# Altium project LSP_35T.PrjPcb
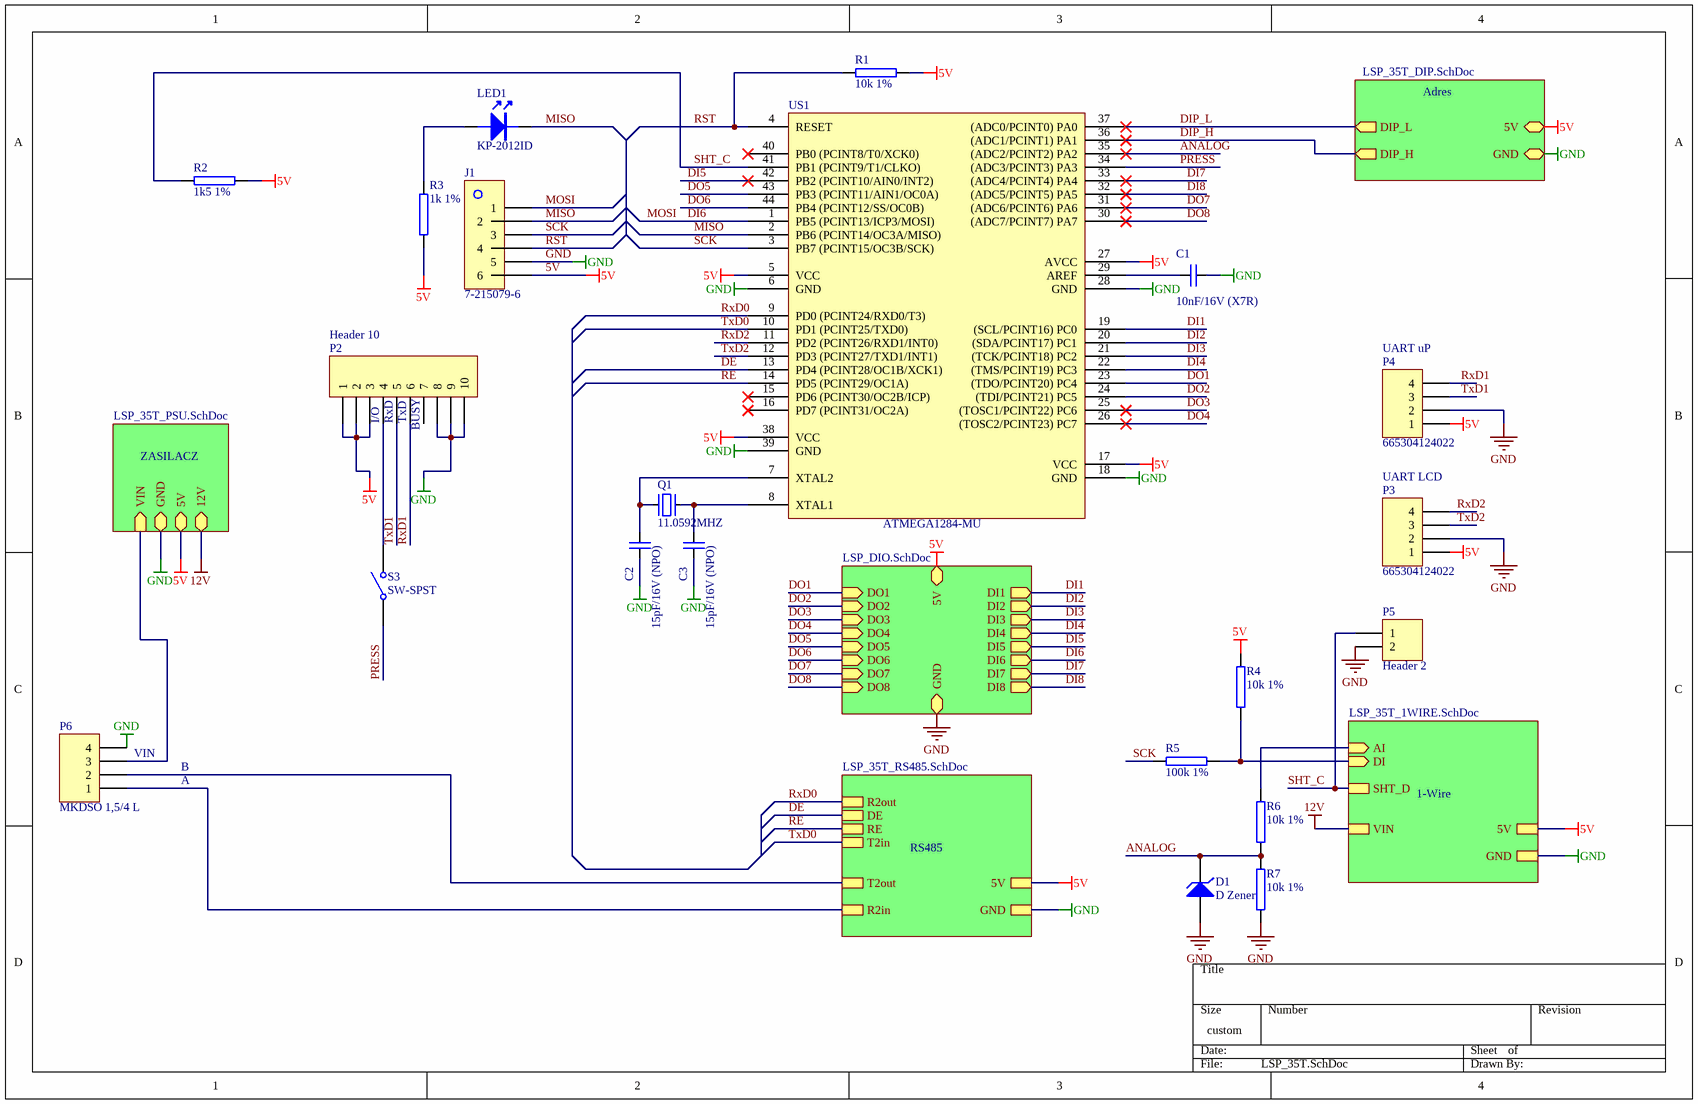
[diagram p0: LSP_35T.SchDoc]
6 sheets, 138 parts. Net scope: hierarchical (ports join the sheet entries above them; power ports are global).
Board files: LSP_35T_Polygon.PcbDoc, LSP_35T.PcbDoc
Sheets:
  LSP_35T.SchDoc
    ZASILACZ = LSP_35T_PSU.SchDoc
    RS485 = LSP_35T_RS485.SchDoc
    Adres = LSP_35T_DIP.SchDoc
    1-Wire = LSP_35T_1WIRE.SchDoc
     = LSP_DIO.SchDoc

## Sheet LSP_35T.SchDoc
size 317 x 205 mm; SheetNumber: 0; SheetTotal: 0

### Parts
C1  10nF/16V (X7R)  [0402]
C2  15pF/16V (NPO)  [0402]
C3  15pF/16V (NPO)  [0402]
D1  D Zener  [minimelf]
J1  7-215079-6  [PRZ_MICROMATCH-6]
LED1  KP-2012ID  [0402d]
P2  Header 10  [FFC/SM1.0-2H10]
P3  665304124022  [665304124022]
P4  665304124022  [665304124022]
P5  Header 2  [665302124022]
P6  MKDSO 1,5/4 L  [HDR1X4]
Q1  11.0592MHZ  [ABM3B]
R1  10k 1%  [0402]
R2  1k5 1%  [0402]
R3  1k 1%  [0402]
R4  10k 1%  [0402]
R5  100k 1%  [0402]
R6  10k 1%  [0402]
R7  10k 1%  [0402]
S3  SW-SPST  [416131160802]
US1  ATMEGA1284-MU  [44A_M]

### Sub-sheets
1-Wire = LSP_35T_1WIRE.SchDoc: AI (in), VIN, GND, 5V, DI (in), SHT_D  | Description: RS485
Adres = LSP_35T_DIP.SchDoc: DIP_L (out), GND (bidir), 5V (bidir), DIP_H (out)  | Description: RS485
RS485 = LSP_35T_RS485.SchDoc: R2out, T2in, T2out, GND, 5V, R2in, DE, RE  | Description: RS485
ZASILACZ = LSP_35T_PSU.SchDoc: VIN (in), GND (bidir), 5V (bidir), 12V (bidir)  | Description: ZASILACZ
? = LSP_DIO.SchDoc: DO1 (in), DO2 (in), DO3 (in), DO4 (in), DO5 (in), DO6 (in), DO7 (in), DO8 (in), DI1 (out), DI2 (out), DI3 (out), DI4 (out), DI5 (out), DI6 (out), DI7 (out), DI8 (out), GND (bidir), 5V (bidir)

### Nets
5V: J1.6 P2.1 P2.2 P2.3 P3.1 P4.1 R1.2 R2.1 R3.1 R4.2 US1.5(VCC) US1.17(VCC) US1.27(AVCC) US1.38(VCC) ; sheet ZASILACZ/5V, sheet RS485/5V, sheet Adres/5V, sheet 1-Wire/5V, sheet /5V
12V: sheet ZASILACZ/12V, sheet 1-Wire/VIN
GND: C1.2 C2.1 C3.1 D1.1(A) J1.5 P2.8 P2.9 P2.10 P3.2 P4.2 P5.2 P6.4 R7.1 US1.6(GND) US1.18(GND) US1.28(GND) US1.39(GND) ; sheet ZASILACZ/GND, sheet RS485/GND, sheet Adres/GND, sheet 1-Wire/GND, sheet /GND
A: P6.1 ; sheet RS485/R2in
ANALOG: D1.2(K) R6.1 R7.2 US1.35((ADC2/PCINT2)_PA2)
B: P6.2 ; sheet RS485/T2out
DE: US1.13(PD4_(PCINT28/OC1B/XCK1)) ; sheet RS485/DE
DI1: US1.19((SCL/PCINT16)_PC0) ; sheet /DI1
DI2: US1.20((SDA/PCINT17)_PC1) ; sheet /DI2
DI3: US1.21((TCK/PCINT18)_PC2) ; sheet /DI3
DI4: US1.22((TMS/PCINT19)_PC3) ; sheet /DI4
DI5: US1.42(PB2_(PCINT10/AIN0/INT2)) ; sheet /DI5
DI6: J1.1 US1.1(PB5_(PCINT13/ICP3/MOSI)) ; sheet /DI6  [also labelled MOSI]
DI7: US1.33((ADC4/PCINT4)_PA4) ; sheet /DI7
DI8: US1.32((ADC5/PCINT5)_PA5) ; sheet /DI8
DIP_H: US1.36((ADC1/PCINT1)_PA1) ; sheet Adres/DIP_H
DIP_L: US1.37((ADC0/PCINT0)_PA0) ; sheet Adres/DIP_L
DO1: US1.23((TDO/PCINT20)_PC4) ; sheet /DO1
DO2: US1.24((TDI/PCINT21)_PC5) ; sheet /DO2
DO3: US1.25((TOSC1/PCINT22)_PC6) ; sheet /DO3
DO4: US1.26((TOSC2/PCINT23)_PC7) ; sheet /DO4
DO5: US1.43(PB3_(PCINT11/AIN1/OC0A)) ; sheet /DO5
DO6: US1.44(PB4_(PCINT12/SS/OC0B)) ; sheet /DO6
DO7: US1.31((ADC6/PCINT6)_PA6) ; sheet /DO7
DO8: US1.30((ADC7/PCINT7)_PA7) ; sheet /DO8
MISO: J1.2 LED1.2 US1.2(PB6_(PCINT14/OC3A/MISO))
PRESS: S3.1(COMMON) US1.34((ADC3/PCINT3)_PA3)
RE: US1.14(PD5_(PCINT29/OC1A)) ; sheet RS485/RE
RST: J1.4 R1.1 US1.4(RESET)
RxD0: US1.9(PD0_(PCINT24/RXD0/T3)) ; sheet RS485/R2out
RxD1: P2.6 P4.4
RxD2: P3.4 US1.11(PD2_(PCINT26/RXD1/INT0))
SCK: J1.3 R5.1 US1.3(PB7_(PCINT15/OC3B/SCK))
SHT_C: P5.1 R2.2 US1.41(PB1_(PCINT9/T1/CLKO)) ; sheet 1-Wire/SHT_D
TxD0: US1.10(PD1_(PCINT25/TXD0)) ; sheet RS485/T2in
TxD1: P2.5 P4.3
TxD2: P3.3 US1.12(PD3_(PCINT27/TXD1/INT1))
NetC1_1: C1.1 US1.29(AREF)
NetC2_2: C2.2 Q1.2 US1.7(XTAL2)
NetC3_2: C3.2 Q1.1 US1.8(XTAL1)
NetD5_1: P6.3 ; sheet ZASILACZ/VIN
NetLED1_1: LED1.1 R3.2
NetP2_4: P2.4 S3.2(NO)
NetP7_5: R4.1 R5.2 ; sheet 1-Wire/DI
NetP7_6: R6.2 ; sheet 1-Wire/AI

Not connected (* = marked no-connect by the designer): P2 7; US1 15(PD6_(PCINT30/OC2B/ICP))* 16(PD7_(PCINT31/OC2A))* 40(PB0_(PCINT8/T0/XCK0))*

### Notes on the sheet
- (near P4) UART uP
- (near P2) I/O
- (near P2) RxD
- (near P2) TxD
- (near P2) BUSY
- (near P3) UART LCD
- (near P6) VIN
- B
- A

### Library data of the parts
C1-C3 = _C_CER: Ceramic capacitor
D1 = D Zener: Zener Diode
LED1 = DIODA2: Dioda LED
P2 = Header 10: Header, 10-Pin
P3 P4 P6 = Header 4: Header, 4-Pin
P5 = Header 2: Header, 2-Pin
Q1 = 11.0592MHZ: Quartz 11,0592MHz, height 3,5mm
R1-R7 = RESSMD1: Rezystor
S3 = SW-SPST: Single-Pole, Single-Throw Switch
US1 = ATMEGA1284-AU

## Sheet LSP_35T_PSU.SchDoc
size A4; SheetNumber: 0; SheetTotal: 0
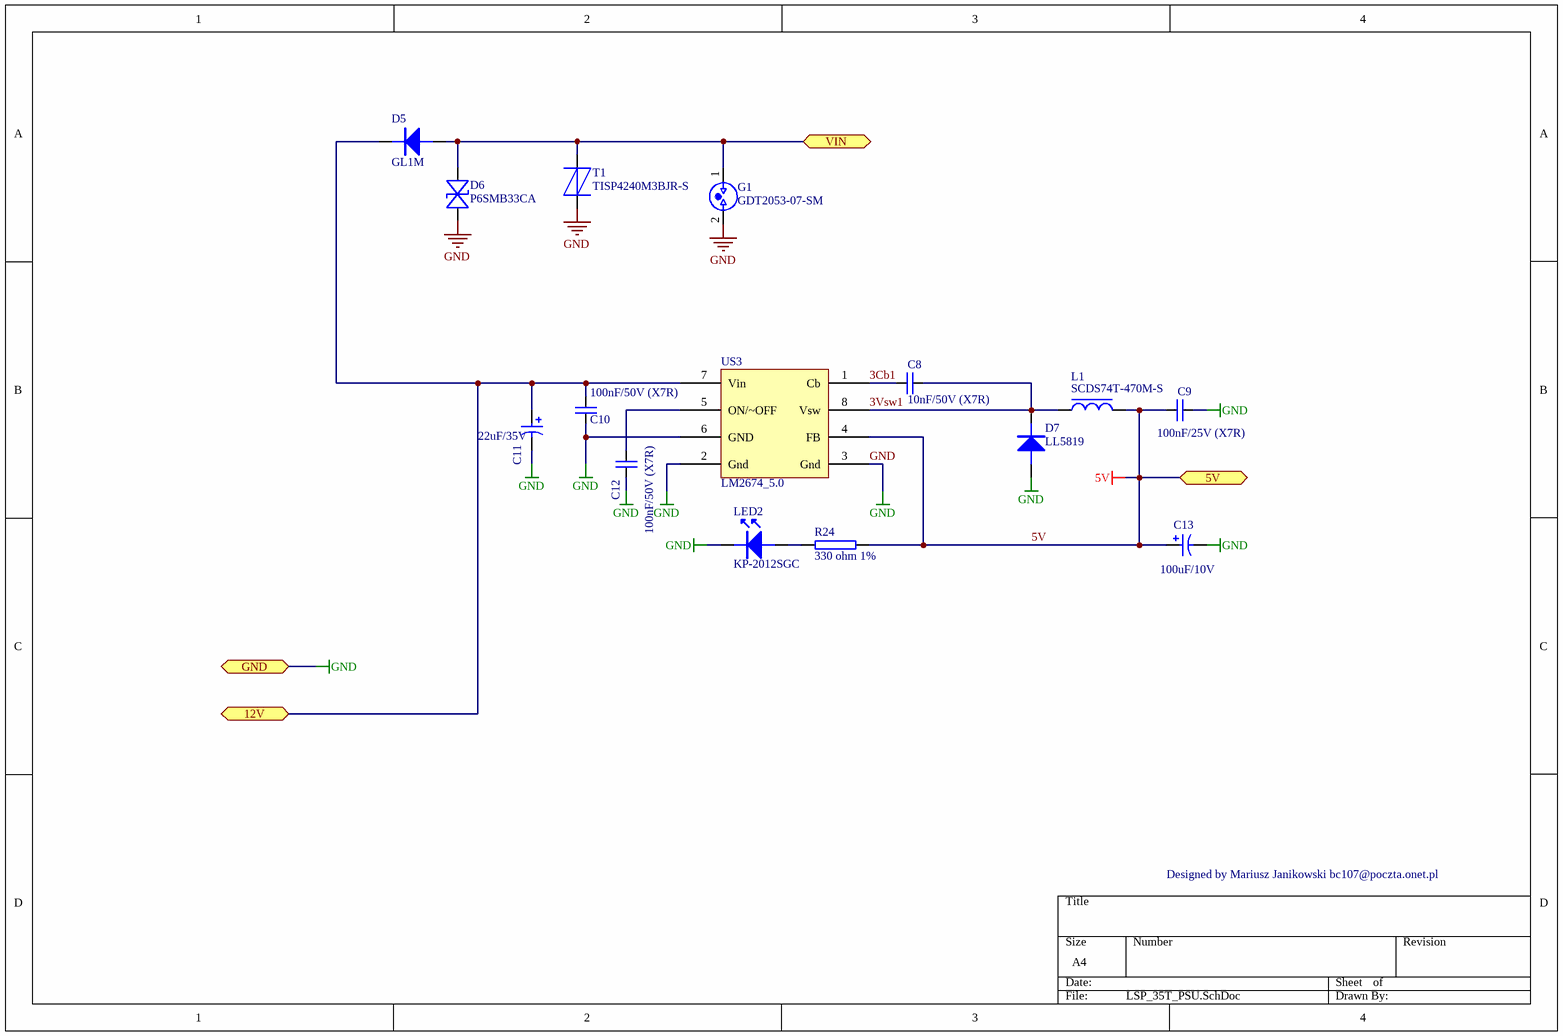
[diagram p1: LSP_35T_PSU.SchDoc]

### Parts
C8  10nF/50V (X7R)  [0402]
C9  100nF/25V (X7R)  [0402]
C10  100nF/50V (X7R)  [0402]
C11  22uF/35V  [SMD_C_TANTAL-D]
C12  100nF/50V (X7R)  [0402]
C13  value 100uF/10V  [TANTAL-B]  (hidden comment: 100uF/16V)
D5  GL1M  [minimelf]
D6  P6SMB33CA  [SMD_DO-214AA/SMB]
D7  LL5819  [SMD_MELF2]
G1  GDT2053-07-SM  [GDT2053]
L1  SCDS74T-470M-S  [SMD_SCDS74T]
LED2  KP-2012SGC  [0402D]
R24  330 ohm 1%  [0402]
T1  TISP4240M3BJR-S  [SMD_DO-214AA/SMB]
US3  LM2674_5.0  [SMD_SO-8]

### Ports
5V, 12V, GND, VIN

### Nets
5V: C9.2 C13.1 L1.2 R24.1 US3.4(FB) ; port 5V
12V: C10.2 C11.1 D5.2 US3.7(Vin) ; port 12V
GND: C9.1 C10.1 C11.2 C12.1 C13.2 D6.1 D7.1 G1.2 LED2.2 T1.2 US3.2(Gnd) US3.3(Gnd) US3.6(GND) ; port GND
3Cb1: C8.1 US3.1(Cb)
3Vsw1: C8.2 D7.2 L1.1 US3.8(Vsw)
NetC12_2: C12.2 US3.5(ON/~OFF)
NetD5_1: D5.1 D6.2 G1.1 T1.1 ; port VIN
NetLED2_1: LED2.1 R24.2

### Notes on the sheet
- Designed by Mariusz Janikowski bc107@poczta.onet.pl

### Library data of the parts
C8-C10 C12 = _C_CER: Ceramic capacitor
C11 C13 = CAP2: Bi-Polar Capacitor
D5 D7 = DIODA1: Dioda
D6 = P6SMB33CA: Transil diode 600W 33V bidirectional; Text Field1: Taiwan Semiconductor; Text Field2: TME
G1 = GDT_1
L1 = CEWKA2
LED2 = DIODA2: Dioda LED
R24 = RESSMD1: Rezystor
T1 = TISP
US3 = LM2675

## Sheet LSP_35T_RS485.SchDoc
size A4; SheetNumber: 0; SheetTotal: 0
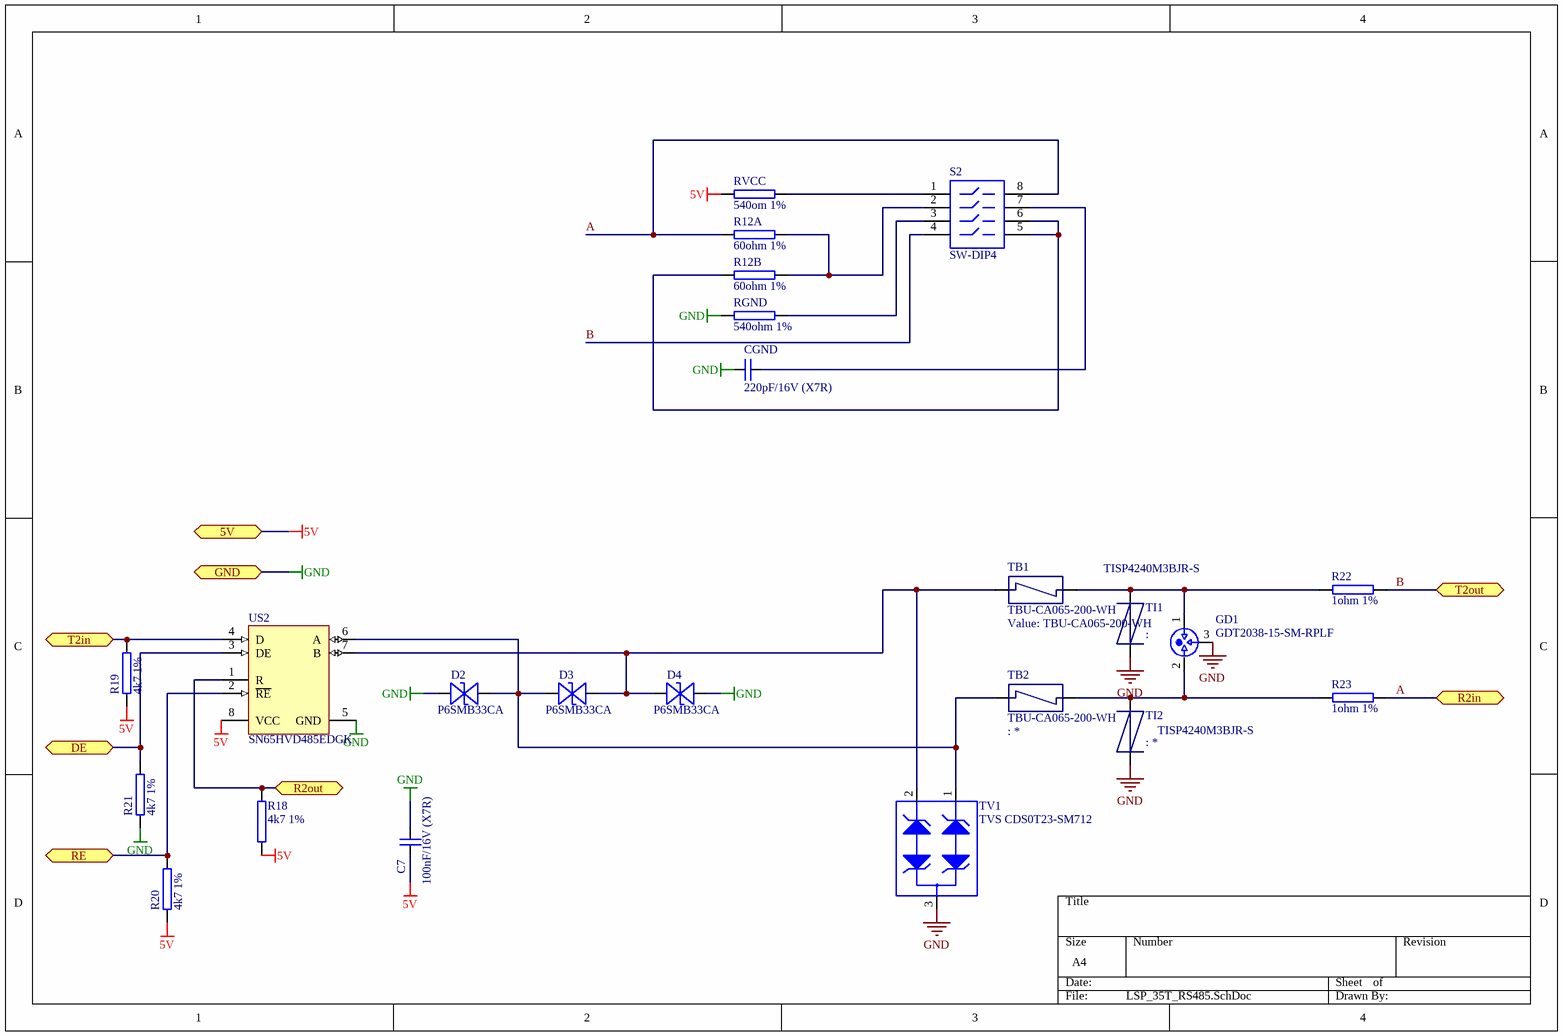
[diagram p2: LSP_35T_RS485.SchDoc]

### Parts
C7  100nF/16V (X7R)  [0402]
CGND  220pF/16V (X7R)  [0402]
D2  P6SMB33CA  [SMD_DO-214AA/SMB]
D3  P6SMB33CA  [SMD_DO-214AA/SMB]
D4  P6SMB33CA  [SMD_DO-214AA/SMB]
GD1  GDT2038-15-SM-RPLF  [GDT2038]
R12A  60ohm 1%  [0402]
R12B  60ohm 1%  [0402]
R18  4k7 1%  [0402]
R19  4k7 1%  [0402]
R20  4k7 1%  [0402]
R21  4k7 1%  [0402]
R22  1ohm 1%  [0402]
R23  1ohm 1%  [0402]
RGND  540ohm 1%  [0402]
RVCC  540om 1%  [0402]
S2  SW-DIP4  [418121270804]
TB1  TBU-CA065-200-WH  [TBU-CA]
TB2  TBU-CA065-200-WH  [TBU-CA]
TI1  TISP4240M3BJR-S  [SMD_DO-214AA/SMB]
TI2  TISP4240M3BJR-S  [SMD_DO-214AA/SMB]
TV1  TVS CDS0T23-SM712  [SOT23]
US2  SN65HVD485EDGK  [DGK8_L]

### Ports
5V, DE, GND, R2in, R2out, RE, T2in, T2out

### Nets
5V: C7.2 R18.1 R19.1 R20.2 RVCC.1 US2.8(VCC) ; port 5V
GND: C7.1 CGND.1 D2.2 D4.1 GD1.3 R21.2 RGND.1 TI1.2 TI2.2 TV1.3 US2.5(GND) ; port GND
A: R12A.1 R23.2 S2.8 ; port R2in
B: R22.2 S2.4 ; port T2out
DE: R21.1 US2.3(DE) ; port DE
RE: R20.1 US2.2(~{RE}) ; port RE
RxD0: R18.2 US2.1(R) ; port R2out
TxD0: R19.2 US2.4(D) ; port T2in
NetCGND_2: CGND.2 S2.7
NetD2_1: D2.1 D3.1 TB2.1 TV1.1 US2.6(A)
NetD3_2: D3.2 D4.2 TB1.1 TV1.2 US2.7(B)
NetGD1_1: GD1.1 R22.1 TB1.2 TI1.1
NetGD1_2: GD1.2 R23.1 TB2.2 TI2.1
NetR12A_2: R12A.2 R12B.2 S2.2
NetR12B_1: R12B.1 S2.5 S2.6
NetRGND_2: RGND.2 S2.3
NetRVCC_2: RVCC.2 S2.1

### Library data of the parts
C7 CGND = _C_CER: Ceramic capacitor
D2-D4 = P6SMB33CA: as D6 on sheet LSP_35T_PSU
GD1 = GDT
R12A R12B R18-R23 RGND RVCC = RESSMD1: Rezystor
S2 = SW-DIP4: DIP Switch
TB1 TB2 = TBU
TI1 TI2 = TISP
TV1 = TVS
US2 = SN65HVD485EDGK: Half Duplex RS-485 Transceiver, 10 Mbps, 5 V, -40 to 85 degC, 8-pin MSOP (DGK), Green (RoHS & no Sb/Br); Manufacturer: Texas Instruments; # of TX/RX: 1 TX / 1 RX; Drivers Per Package: 1; Number of Nodes: 64; Signaling Rate(Mbps): 10; Common Mode Range: -7 to 12; ESD(kV): 15; Fault Protection(V): -9 to 14; Fail Safe: Open; ICC(Max)(mA): 2; Supply Voltage(s)(V): 5; Rating: Catalog

## Sheet LSP_35T_DIP.SchDoc
size A4; SheetNumber: 0; SheetTotal: 0
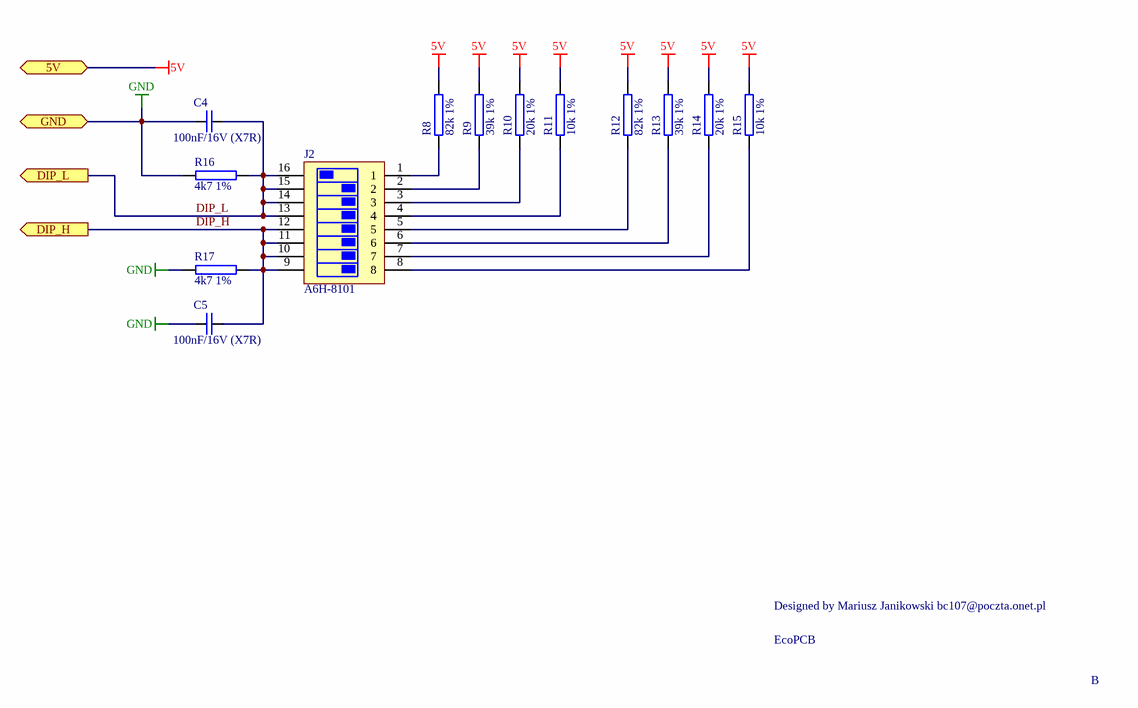
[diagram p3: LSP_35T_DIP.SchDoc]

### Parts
C4  100nF/16V (X7R)  [0402]
C5  100nF/16V (X7R)  [0402]
J2  A6H-8101  [DIP8]
R8  82k 1%  [0402]
R9  39k 1%  [0402]
R10  20k 1%  [0402]
R11  10k 1%  [0402]
R12  82k 1%  [0402]
R13  39k 1%  [0402]
R14  20k 1%  [0402]
R15  10k 1%  [0402]
R16  4k7 1%  [0402]
R17  4k7 1%  [0402]

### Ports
5V (bidir), DIP_H (out), DIP_L (out), GND (bidir)

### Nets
5V: R8.1 R9.1 R10.1 R11.1 R12.1 R13.1 R14.1 R15.1 ; port 5V
GND: C4.2 C5.2 R16.2 R17.2 ; port GND
DIP_H: C5.1 J2.9 J2.10 J2.11 J2.12 R17.1 ; port DIP_H
DIP_L: C4.1 J2.13 J2.14 J2.15 J2.16 R16.1 ; port DIP_L
NetJ2_1: J2.1 R8.2
NetJ2_2: J2.2 R9.2
NetJ2_3: J2.3 R10.2
NetJ2_4: J2.4 R11.2
NetJ2_5: J2.5 R12.2
NetJ2_6: J2.6 R13.2
NetJ2_7: J2.7 R14.2
NetJ2_8: J2.8 R15.2

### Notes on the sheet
- Designed by Mariusz Janikowski bc107@poczta.onet.pl
- EcoPCB
- B

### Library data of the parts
C4 C5 = _C_CER: Ceramic capacitor
J2 = DIPSWITCH
R8-R17 = RESSMD1: Rezystor

## Sheet LSP_35T_1WIRE.SchDoc
size A4
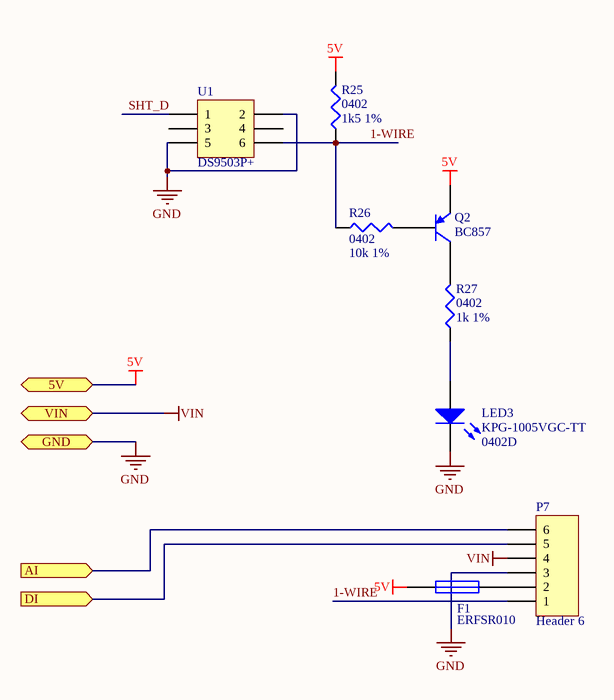
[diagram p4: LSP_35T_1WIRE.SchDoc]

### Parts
F1  ERFSR010  [6-0805_L]
LED3  KPG-1005VGC-TT  [0402D]
P7  Header 6  [PT1,5/6-PVH-3,5]
Q2  BC857  [NXP-SOT23_L]
R25  value 1k5 1%  [0402]
R26  value 10k 1%  [0402]
R27  value 1k 1%  [0402]
U1  DS9503P+  [TSOC6]

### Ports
5V, AI (in), DI (in), GND, VIN

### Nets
5V: F1.1 Q2.2(E) R25.2 ; port 5V
GND: LED3.2(K) P7.3 U1.2 U1.5 ; port GND
VIN: P7.4 ; port VIN  [project net 12V]
1-WIRE: P7.1 R25.1 R26.1 U1.6
SHT_D: U1.1
NetF1_2: F1.2 P7.2
NetLED3_1: LED3.1(A) R27.1
NetP7_5: P7.5 ; port DI
NetP7_6: P7.6 ; port AI
NetQ2_1: Q2.1(B) R26.2
NetQ2_3: Q2.3(C) R27.2

Not connected (* = marked no-connect by the designer): U1 3 4

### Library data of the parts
F1 = Fuse 1: Fuse
LED3 = LED2: Typical RED, GREEN, YELLOW, AMBER GaAs LED
P7 = Header 6: Header, 6-Pin
Q2 = 2N3906: PNP General Purpose Amplifier
R25-R27 = Res3: Resistor
U1 = Header 3X2: Header, 3-Pin, Dual row

## Sheet LSP_DIO.SchDoc
size A4
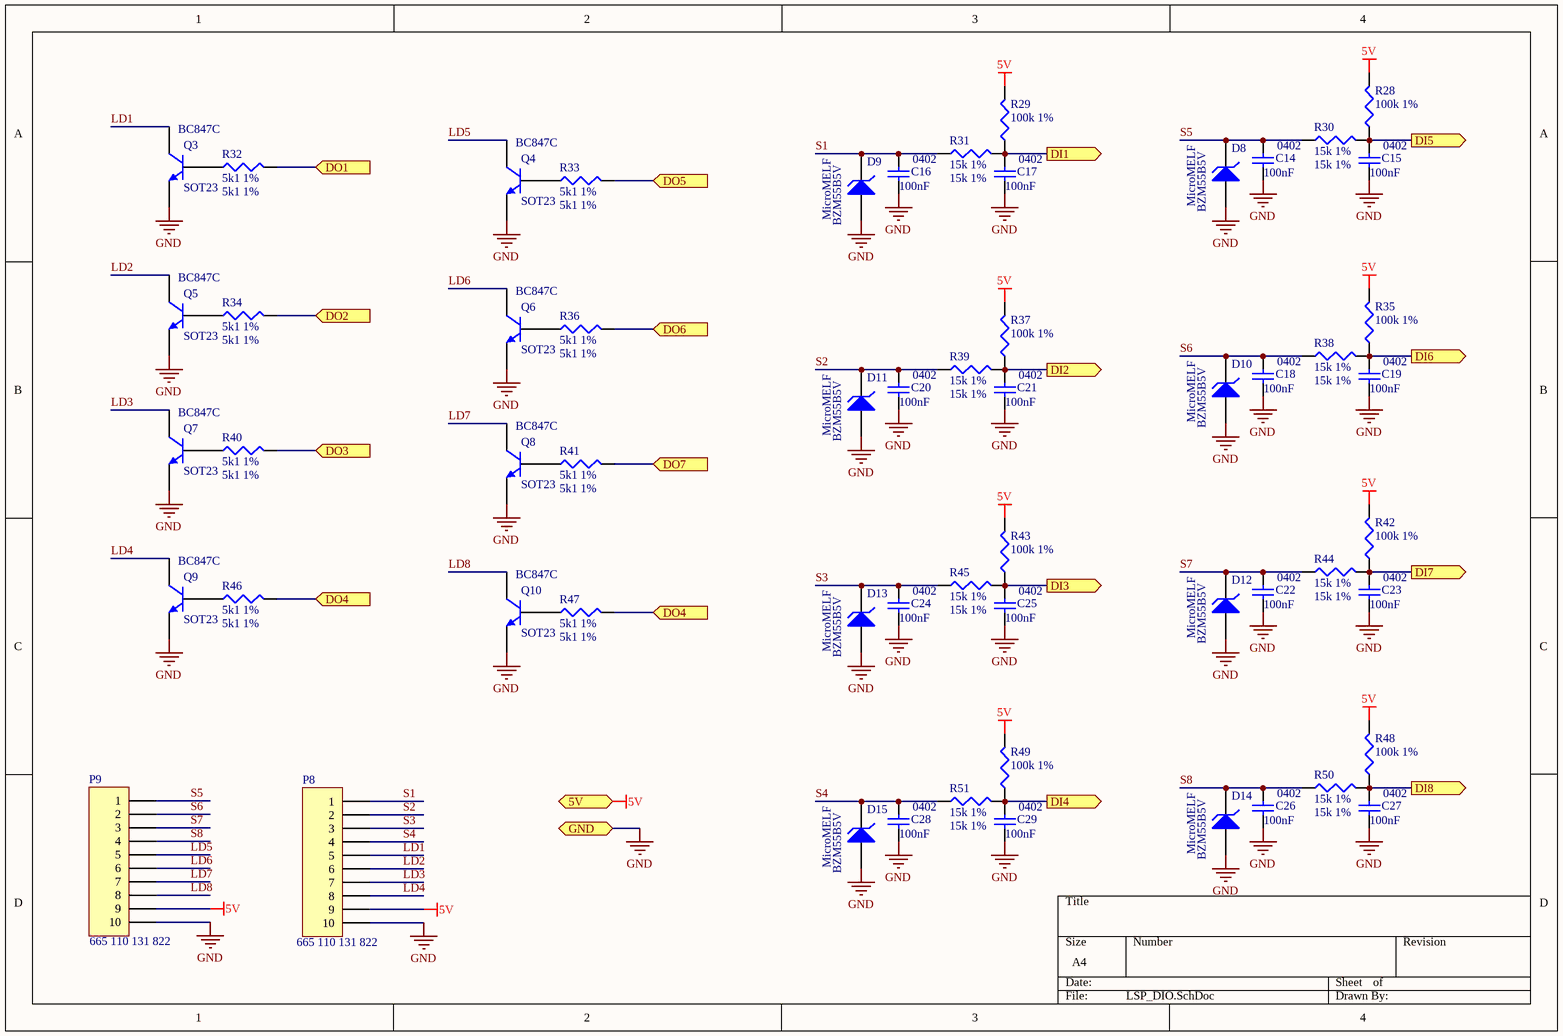
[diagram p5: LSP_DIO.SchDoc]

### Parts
C14  value 100nF  [0402]  (hidden comment: Cap Semi)
C15  value 100nF  [0402]  (hidden comment: Cap Semi)
C16  value 100nF  [0402]  (hidden comment: Cap Semi)
C17  value 100nF  [0402]  (hidden comment: Cap Semi)
C18  value 100nF  [0402]  (hidden comment: Cap Semi)
C19  value 100nF  [0402]  (hidden comment: Cap Semi)
C20  value 100nF  [0402]  (hidden comment: Cap Semi)
C21  value 100nF  [0402]  (hidden comment: Cap Semi)
C22  value 100nF  [0402]  (hidden comment: Cap Semi)
C23  value 100nF  [0402]  (hidden comment: Cap Semi)
C24  value 100nF  [0402]  (hidden comment: Cap Semi)
C25  value 100nF  [0402]  (hidden comment: Cap Semi)
C26  value 100nF  [0402]  (hidden comment: Cap Semi)
C27  value 100nF  [0402]  (hidden comment: Cap Semi)
C28  value 100nF  [0402]  (hidden comment: Cap Semi)
C29  value 100nF  [0402]  (hidden comment: Cap Semi)
D8  BZM55B5V  [MicroMELF]
D9  BZM55B5V  [MicroMELF]
D10  BZM55B5V  [MicroMELF]
D11  BZM55B5V  [MicroMELF]
D12  BZM55B5V  [MicroMELF]
D13  BZM55B5V  [MicroMELF]
D14  BZM55B5V  [MicroMELF]
D15  BZM55B5V  [MicroMELF]
P8  665 110 131 822  [665110131822]
P9  665 110 131 822  [665110131822]
Q3  BC847C  PackageReference: SOT23  [SOT23_L]
Q4  BC847C  PackageReference: SOT23  [SOT23_L]
Q5  BC847C  PackageReference: SOT23  [SOT23_L]
Q6  BC847C  PackageReference: SOT23  [SOT23_L]
Q7  BC847C  PackageReference: SOT23  [SOT23_L]
Q8  BC847C  PackageReference: SOT23  [SOT23_L]
Q9  BC847C  PackageReference: SOT23  [SOT23_L]
Q10  BC847C  PackageReference: SOT23  [SOT23_L]
R28  100k 1%  [0402]
R29  100k 1%  [0402]
R30  15k 1%  [0402]
R31  15k 1%  [0402]
R32  5k1 1%  [0402]
R33  5k1 1%  [0402]
R34  5k1 1%  [0402]
R35  100k 1%  [0402]
R36  5k1 1%  [0402]
R37  100k 1%  [0402]
R38  15k 1%  [0402]
R39  15k 1%  [0402]
R40  5k1 1%  [0402]
R41  5k1 1%  [0402]
R42  100k 1%  [0402]
R43  100k 1%  [0402]
R44  15k 1%  [0402]
R45  15k 1%  [0402]
R46  5k1 1%  [0402]
R47  5k1 1%  [0402]
R48  100k 1%  [0402]
R49  100k 1%  [0402]
R50  15k 1%  [0402]
R51  15k 1%  [0402]

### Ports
5V (bidir), DI1 (out), DI2 (out), DI3 (out), DI4 (out), DI5 (out), DI6 (out), DI7 (out), DI8 (out), DO1 (in), DO2 (in), DO3 (in), DO4 (in), DO5 (in), DO6 (in), DO7 (in), GND (bidir)

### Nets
5V: P8.9 P9.9 R28.2 R29.2 R35.2 R37.2 R42.2 R43.2 R48.2 R49.2 ; port 5V
GND: C14.1 C15.1 C16.1 C17.1 C18.1 C19.1 C20.1 C21.1 C22.1 C23.1 C24.1 C25.1 C26.1 C27.1 C28.1 C29.1 D8.1(A) D9.1(A) D10.1(A) D11.1(A) D12.1(A) D13.1(A) D14.1(A) D15.1(A) P8.10 P9.10 Q3.2(E) Q4.2(E) Q5.2(E) Q6.2(E) Q7.2(E) Q8.2(E) Q9.2(E) Q10.2(E) ; port GND
DI1: C17.2 R29.1 R31.2 ; port DI1
DI2: C21.2 R37.1 R39.2 ; port DI2
DI3: C25.2 R43.1 R45.2 ; port DI3
DI4: C29.2 R49.1 R51.2 ; port DI4
DI5: C15.2 R28.1 R30.2 ; port DI5
DI6: C19.2 R35.1 R38.2 ; port DI6
DI7: C23.2 R42.1 R44.2 ; port DI7
DI8: C27.2 R48.1 R50.2 ; port DI8
DO1: R32.2 ; port DO1
DO2: R34.2 ; port DO2
DO3: R40.2 ; port DO3
DO4: R46.2 R47.2 ; port DO4
DO5: R33.2 ; port DO5
DO6: R36.2 ; port DO6
DO7: R41.2 ; port DO7
LD1: P8.5 Q3.1(C)
LD2: P8.6 Q5.1(C)
LD3: P8.7 Q7.1(C)
LD4: P8.8 Q9.1(C)
LD5: P9.5 Q4.1(C)
LD6: P9.6 Q6.1(C)
LD7: P9.7 Q8.1(C)
LD8: P9.8 Q10.1(C)
S1: C16.2 D9.2(K) P8.1 R31.1
S2: C20.2 D11.2(K) P8.2 R39.1
S3: C24.2 D13.2(K) P8.3 R45.1
S4: C28.2 D15.2(K) P8.4 R51.1
S5: C14.2 D8.2(K) P9.1 R30.1
S6: C18.2 D10.2(K) P9.2 R38.1
S7: C22.2 D12.2(K) P9.3 R44.1
S8: C26.2 D14.2(K) P9.4 R50.1
NetQ3_3: Q3.3(B) R32.1
NetQ4_3: Q4.3(B) R33.1
NetQ5_3: Q5.3(B) R34.1
NetQ6_3: Q6.3(B) R36.1
NetQ7_3: Q7.3(B) R40.1
NetQ8_3: Q8.3(B) R41.1
NetQ9_3: Q9.3(B) R46.1
NetQ10_3: Q10.3(B) R47.1

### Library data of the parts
C14-C29 = Cap Semi: Capacitor (Semiconductor SIM Model)
D8-D15 = D Zener: Zener Diode
P8 P9 = Header 10: Header, 10-Pin
Q3-Q10 = 2N3904: NPN General Purpose Amplifier
R28-R51 = Res3: Resistor

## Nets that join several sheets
5V: LSP_35T (14 pins), LSP_35T_PSU (5 pins), LSP_35T_RS485 (6 pins), LSP_35T_DIP (8 pins), LSP_35T_1WIRE (F1.1 Q2.2 R25.2), LSP_DIO (10 pins)
12V: LSP_35T_PSU (C10.2 C11.1 D5.2 US3.7), LSP_35T_1WIRE (P7.4)
GND: LSP_35T (17 pins), LSP_35T_PSU (13 pins), LSP_35T_RS485 (11 pins), LSP_35T_DIP (C4.2 C5.2 R16.2 R17.2), LSP_35T_1WIRE (LED3.2 P7.3 U1.2 U1.5), LSP_DIO (34 pins)
A: LSP_35T (P6.1), LSP_35T_RS485 (R12A.1 R23.2 S2.8)
B: LSP_35T (P6.2), LSP_35T_RS485 (R22.2 S2.4)
DE: LSP_35T (US1.13), LSP_35T_RS485 (R21.1 US2.3)
DI1: LSP_35T (US1.19), LSP_DIO (C17.2 R29.1 R31.2)
DI2: LSP_35T (US1.20), LSP_DIO (C21.2 R37.1 R39.2)
DI3: LSP_35T (US1.21), LSP_DIO (C25.2 R43.1 R45.2)
DI4: LSP_35T (US1.22), LSP_DIO (C29.2 R49.1 R51.2)
DI5: LSP_35T (US1.42), LSP_DIO (C15.2 R28.1 R30.2)
DI6: LSP_35T (J1.1 US1.1), LSP_DIO (C19.2 R35.1 R38.2)
DI7: LSP_35T (US1.33), LSP_DIO (C23.2 R42.1 R44.2)
DI8: LSP_35T (US1.32), LSP_DIO (C27.2 R48.1 R50.2)
DIP_H: LSP_35T (US1.36), LSP_35T_DIP (6 pins)
DIP_L: LSP_35T (US1.37), LSP_35T_DIP (6 pins)
DO1: LSP_35T (US1.23), LSP_DIO (R32.2)
DO2: LSP_35T (US1.24), LSP_DIO (R34.2)
DO3: LSP_35T (US1.25), LSP_DIO (R40.2)
DO4: LSP_35T (US1.26), LSP_DIO (R46.2 R47.2)
DO5: LSP_35T (US1.43), LSP_DIO (R33.2)
DO6: LSP_35T (US1.44), LSP_DIO (R36.2)
DO7: LSP_35T (US1.31), LSP_DIO (R41.2)
NetD5_1: LSP_35T (P6.3), LSP_35T_PSU (D5.1 D6.2 G1.1 T1.1)
NetP7_5: LSP_35T (R4.1 R5.2), LSP_35T_1WIRE (P7.5)
NetP7_6: LSP_35T (R6.2), LSP_35T_1WIRE (P7.6)
RE: LSP_35T (US1.14), LSP_35T_RS485 (R20.1 US2.2)
RxD0: LSP_35T (US1.9), LSP_35T_RS485 (R18.2 US2.1)
TxD0: LSP_35T (US1.10), LSP_35T_RS485 (R19.2 US2.4)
